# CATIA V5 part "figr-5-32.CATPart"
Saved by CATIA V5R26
Part number: Part1
Bounding box of the stored display mesh (mm): x -32.491 to 32.491, y -32.393 to 32.393, z 0 to 85.656
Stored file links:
  D:\_Deepak\CATIA\CATIA V5-6R2016_Deepak\Resources\Part files\Partfiles\c05_catia_v5_6r2016_prt\figr-5-32.CATPart
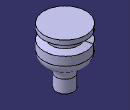
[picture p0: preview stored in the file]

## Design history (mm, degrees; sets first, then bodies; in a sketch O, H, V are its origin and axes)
Body1 (main body)
  Sketch1 on yz-plane, origin (0, 0, 0), H (0, 1, 0), V (0, 0, 1)
    axis line L1 (0, 0) -> (0, 100.0993)
    line L2 (0, 0) -> (13.3295, 0)
    line L3 (13.3295, 0) -> (13.3295, 19.6564)
    arc A1 centre (31.7623, 19.6564) radius 18.4328 from (13.3295, 19.6564) to (23.518, 36.1427) cw
    arc A2 centre (16.25, 50.6768) radius 16.25 from (23.518, 36.1427) to (32.5, 50.6768) ccw
    line L4 (32.5, 50.6768) -> (32.5, 85.6563)
    line L5 (32.5, 85.6563) -> (0, 85.6563)
    point P9 (0, 85.6563)
    line L6 (0, 85.6563) -> (0, 0)
    radius about axis L4 L1 = 32.5
    vertical: L1 V, L3 V, L4 V
    horizontal: L2 H, L5 H
    tangency: A1 L3, A2 L1, A2 A1, L4 A2, L6 A2
    coincidence: P9 L1
  Shaft1: profile Sketch1, axis Sketch1.L1, angle 360
  Sketch2 on yz-plane, origin (0, 0, 0), H (0, 1, 0), V (0, 0, 1)
    axis line L1 (0, 0) -> (0, 91.1904)
    point P1 (0, 0)
    point P2 (0, 91.1904)
    line L2 (32.5, 78.7512) -> (21.4593, 75.7196)
    line L3 (21.4593, 75.7196) -> (21.4593, 66.4534)
    line L4 (21.4593, 66.4534) -> (32.5, 63.9927)
    line L5 (32.5, 63.9927) -> (32.5, 78.7512)
    coincidence: P1 H, P2 V
    vertical: L1 V, L3 V, L5 V
  Groove1: profile Sketch2, axis Sketch2.L1, angle 360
